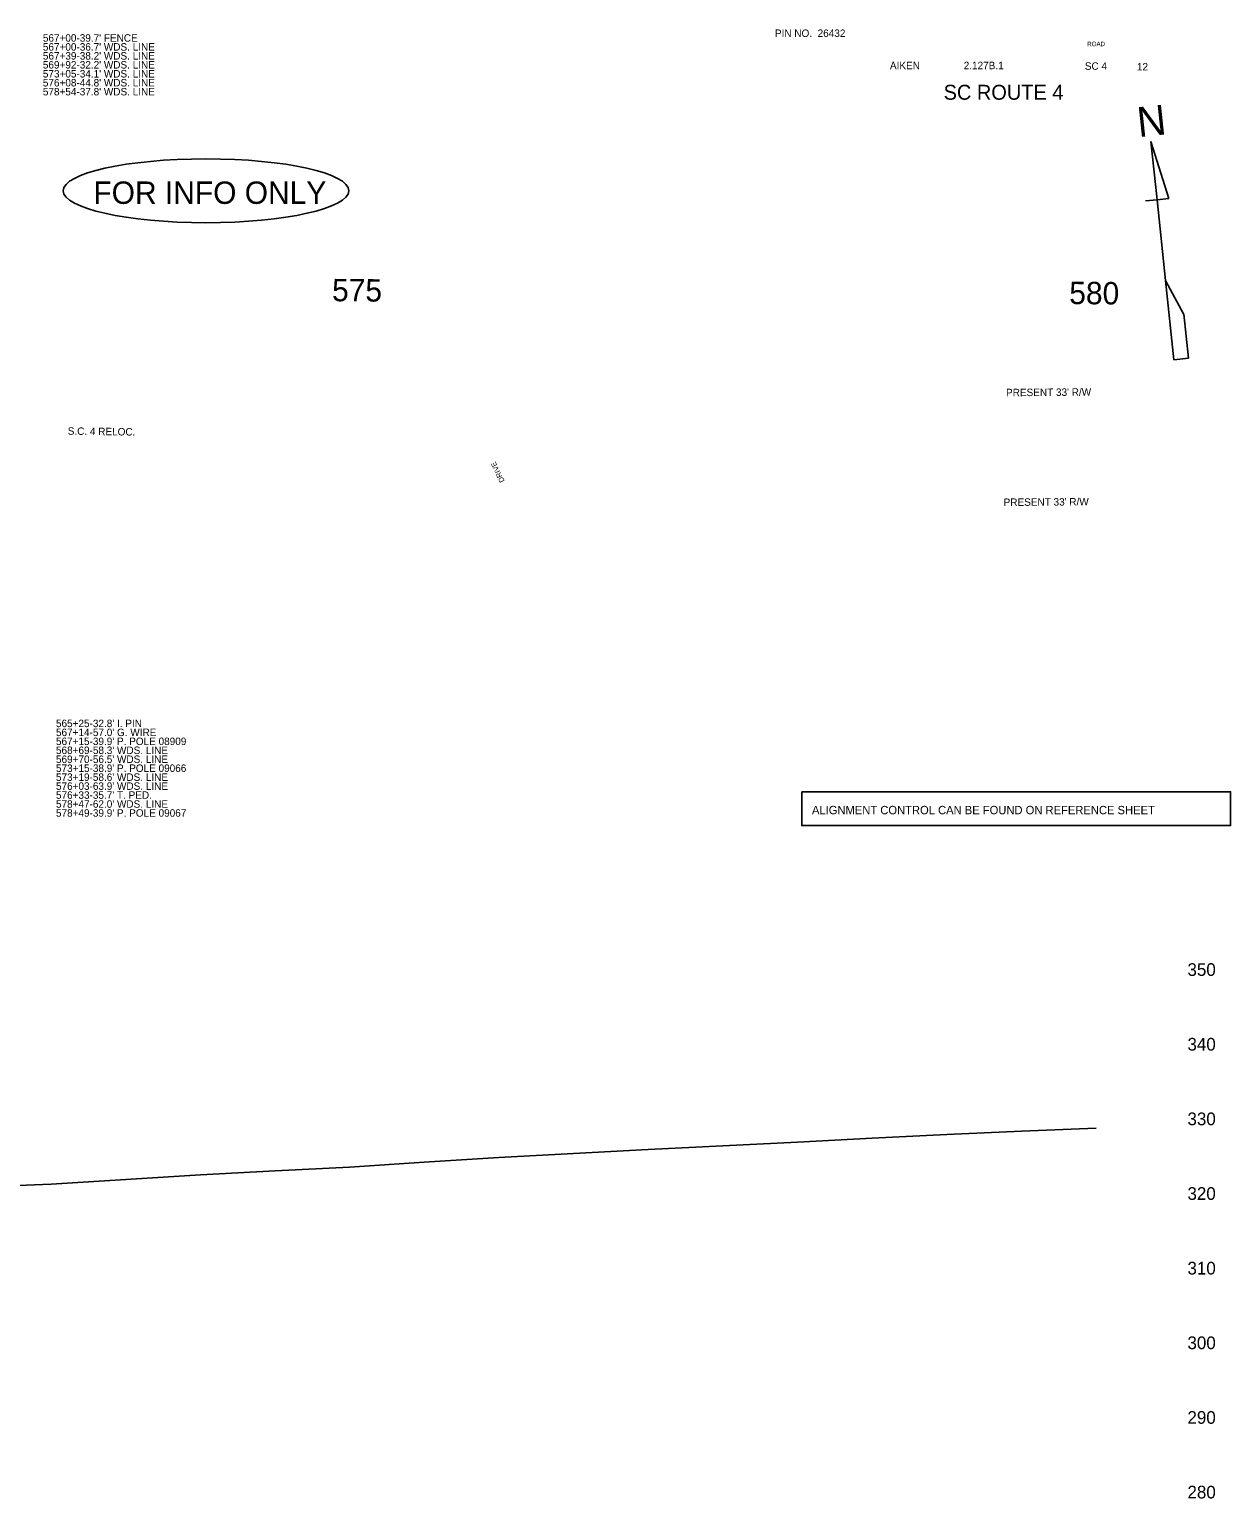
# Model space of a CAD drawing. Extents: x 49105 to 50775, y 45514 to 53458.
# Drawn here: x 49970 to 50775, y 52474 to 53458 of the extents above; entities that cross this region are included whole.
import ezdxf

# ---------------------------------------------------------------- set-up
doc = ezdxf.new("R2010")
doc.units = 0
for name, color, linetype in [('Level 1', 7, 'Continuous'), ('Level 19', 7, 'Continuous'), ('Level 2', 7, 'Continuous'), ('Level 24', 7, 'Continuous'), ('Level 25', 7, 'Continuous'), ('Level 39', 7, 'Continuous'), ('Level 40', 7, 'Continuous'), ('Level 42', 7, 'Continuous'), ('Level 8', 7, 'Continuous')]:
    doc.layers.add(name, color=color, linetype=linetype)

msp = doc.modelspace()

# ---------------------------------------------------------------- linework, layer by layer
at = {"layer": 'Level 19'}
msp.add_ellipse((50088.33, 53349.88), major_axis=(95.67, 0), ratio=0.223378, dxfattribs=at)
at = {"layer": 'Level 2'}
for p, q in [((50733.26, 53344.72), (50721.36, 53382.89)), ((50721.36, 53382.89), (50721.36, 53382.89)), ((50721.36, 53382.89), (50725.46, 53343.9)), ((50717.66, 53343.08), (50725.46, 53343.9)), ((50725.46, 53343.9), (50733.26, 53344.72)), ((50731.15, 53289.8), (50725.46, 53343.9)), ((50733.26, 53344.72), (50733.21, 53345.18)), ((50743.4, 53266.95), (50731.15, 53289.8)), ((50731.15, 53289.8), (50736.73, 53236.69)), ((50746.47, 53237.71), (50743.37, 53267.22)), ((50743.37, 53267.22), (50743.4, 53266.95)), ((50736.73, 53236.69), (50746.47, 53237.71))]:
    msp.add_line(p, q, dxfattribs=at)
at = {"layer": 'Level 25'}
msp.add_lwpolyline([(50487.39, 52947.35), (50774.72, 52947.35), (50774.72, 52924.63), (50487.39, 52924.63)], close=True, dxfattribs=at)
at = {"layer": 'Level 40'}
msp.add_lwpolyline([(49934.59, 52682.48), (49984.59, 52684.55), (50034.59, 52687.67), (50084.59, 52690.8), (50134.59, 52693.38), (50184.59, 52695.95), (50234.59, 52699.18), (50284.59, 52702.4), (50334.59, 52705.03), (50384.59, 52707.65), (50434.59, 52710.1), (50484.59, 52712.55), (50534.59, 52715.18), (50584.59, 52717.8), (50634.59, 52719.9), (50684.58, 52722)], dxfattribs=at)

# ---------------------------------------------------------------- texts
at = {"layer": 'Level 1'}
for p in [(50624.31, 53212.22), (50622.69, 53138.74)]:
    msp.add_text("PRESENT 33' R/W", height=5, rotation=0.40349, dxfattribs=at).set_placement(p)
at = {"layer": 'Level 19'}
msp.add_text('FOR INFO ONLY', height=15, dxfattribs=at).set_placement((50012.93, 53341.1))
for s, p in [('575', (50172.76, 53275.91)), ('580', (50666.58, 53274))]:
    msp.add_text(s, height=15, rotation=359.49443, dxfattribs=at).set_placement(p)
at = {"layer": 'Level 2'}
msp.add_text('N', height=20, rotation=6, dxfattribs=at).set_placement((50713.13, 53385.75))
at = {"layer": 'Level 24'}
for s, height, p in [("567+00-39.7' FENCE", 5, (49979.08, 53449.75)), ('PIN NO.  26432', 5, (50469.47, 53452.91)), ('ROAD', 3, (50678.66, 53446.73)), ("567+00-36.7' WDS. LINE", 5, (49979.08, 53443.75)), ("567+39-38.2' WDS. LINE", 5, (49979.08, 53437.75)), ("569+92-32.2' WDS. LINE", 5, (49979.08, 53431.75)), ("573+05-34.1' WDS. LINE", 5, (49979.08, 53425.75)), ('AIKEN', 5, (50546.51, 53431.32)), (' 2.127B.1', 5, (50594.07, 53431.32)), ('SC 4', 5, (50677.06, 53430.93)), ('12', 5, (50711.97, 53430.45)), ("576+08-44.8' WDS. LINE", 5, (49979.08, 53419.75)), ('SC ROUTE 4', 10, (50582.48, 53410.85)), ("578+54-37.8' WDS. LINE", 5, (49979.08, 53413.75)), ("565+25-32.8' I. PIN", 5, (49987.86, 52990.6)), ("567+14-57.0' G. WIRE", 5, (49987.86, 52984.6)), ("567+15-39.9' P. POLE 08909", 5, (49987.86, 52978.6)), ("568+69-58.3' WDS. LINE", 5, (49987.86, 52972.6)), ("569+70-56.5' WDS. LINE", 5, (49987.86, 52966.6)), ("573+15-38.9' P. POLE 09066", 5, (49987.86, 52960.6)), ("573+19-58.6' WDS. LINE", 5, (49987.86, 52954.6)), ("576+03-63.9' WDS. LINE", 5, (49987.86, 52948.6)), ("576+33-35.7' T. PED.", 5, (49987.86, 52942.6)), ("578+47-62.0' WDS. LINE", 5, (49987.86, 52936.6)), ("578+49-39.9' P. POLE 09067", 5, (49987.86, 52930.6))]:
    msp.add_text(s, height=height, dxfattribs=at).set_placement(p)
at = {"layer": 'Level 25'}
msp.add_text('ALIGNMENT CONTROL CAN BE FOUND ON REFERENCE SHEET', height=5.6, dxfattribs=at).set_placement((50494.29, 52932.24))
at = {"layer": 'Level 39'}
msp.add_text('S.C. 4 RELOC.', height=5, rotation=359.22455, dxfattribs=at).set_placement((49995.7, 53186.47))
at = {"layer": 'Level 42'}
for s, p in [('350', (50745.8, 52823.95)), ('340', (50745.8, 52773.95)), ('330', (50745.8, 52723.95)), ('320', (50745.8, 52673.95)), ('310', (50745.8, 52623.95)), ('300', (50745.8, 52573.95)), ('290', (50745.8, 52523.95)), ('280', (50745.8, 52473.95))]:
    msp.add_text(s, height=8.5, dxfattribs=at).set_placement(p)
at = {"layer": 'Level 8'}
msp.add_text('DRIVE', height=3.5, rotation=115.73869, dxfattribs=at).set_placement((50288.5, 53155.49))

doc.saveas('drawing.dxf')
